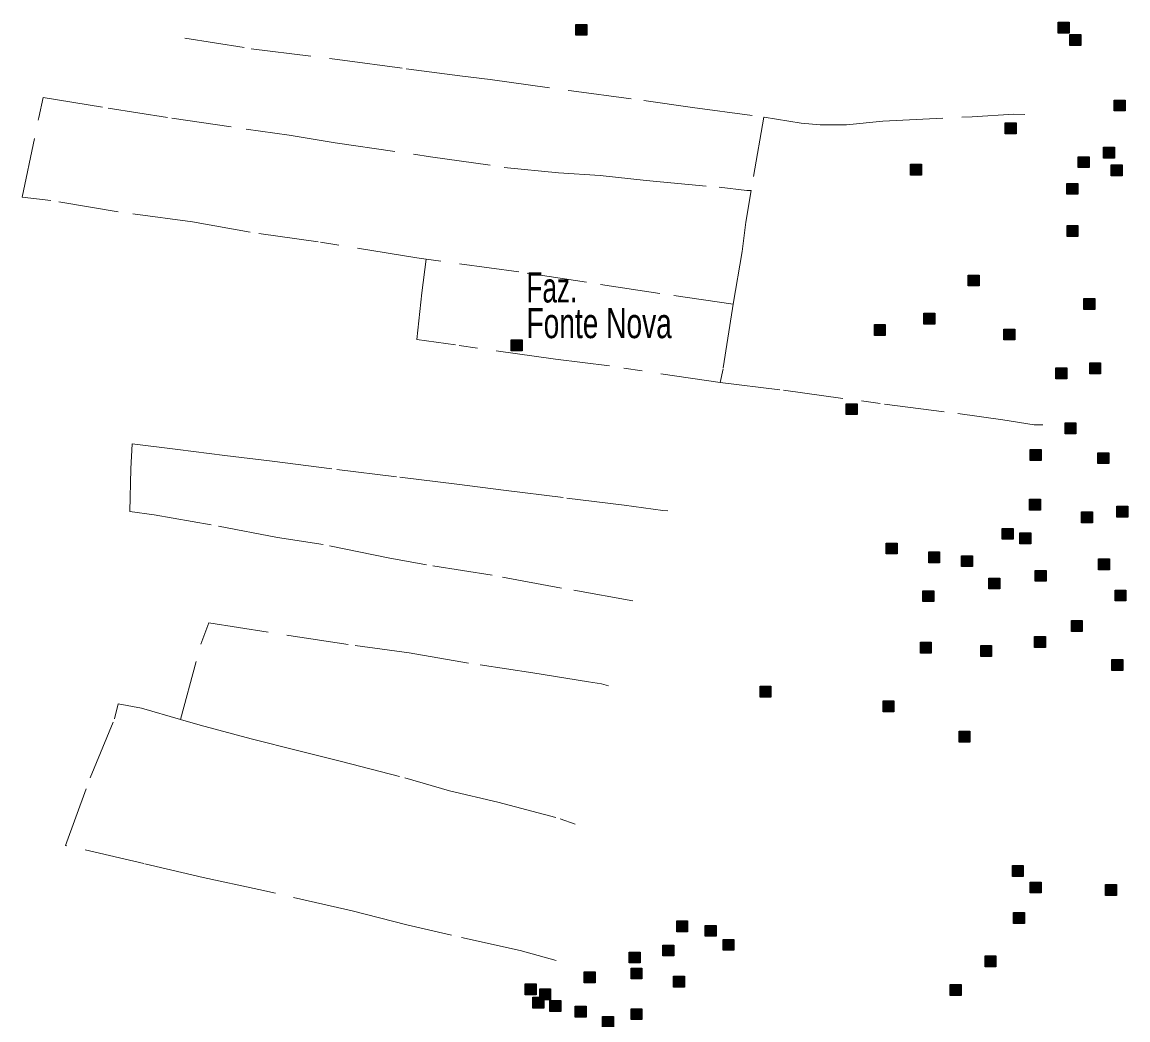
# Model space of a CAD drawing. Extents: x 445.6 to 500, y 8618.1 to 8673.4.
# Drawn here: x 494.02 to 499.91, y 8658.81 to 8664.13 of the extents above; entities that cross this region are included whole.
import ezdxf

# ---------------------------------------------------------------- set-up
doc = ezdxf.new("R2010")
doc.units = 0
doc.header["$LTSCALE"] = 0.064
doc.linetypes.add('DOT_DASHED', pattern=[7.7, 5, -1.2, 0.3, -1.2])
doc.layers.add('2', color=7, linetype='Continuous', lineweight=25)
doc.layers.add('22', color=7, linetype='DOT_DASHED', lineweight=13)
doc.layers.add('61', color=7, linetype='Continuous')

msp = doc.modelspace()

# ---------------------------------------------------------------- hatches: boundary and pattern name
at = {"layer": '2'}
for points in [[(496.9698, 8664.1133), (497.0278, 8664.1133), (497.0278, 8664.0553), (496.9698, 8664.0553)], [(499.5395, 8664.1252), (499.5975, 8664.1252), (499.5975, 8664.0672), (499.5395, 8664.0672)], [(499.602, 8664.0591), (499.66, 8664.0591), (499.66, 8664.0011), (499.602, 8664.0011)], [(499.8385, 8663.7101), (499.8965, 8663.7101), (499.8965, 8663.6521), (499.8385, 8663.6521)], [(499.2575, 8663.5882), (499.3155, 8663.5882), (499.3155, 8663.5302), (499.2575, 8663.5302)], [(499.7811, 8663.4594), (499.8391, 8663.4594), (499.8391, 8663.4014), (499.7811, 8663.4014)], [(499.646, 8663.4086), (499.704, 8663.4086), (499.704, 8663.3506), (499.646, 8663.3506)], [(498.7525, 8663.368), (498.8105, 8663.368), (498.8105, 8663.31), (498.7525, 8663.31)], [(499.8216, 8663.3646), (499.8796, 8663.3646), (499.8796, 8663.3066), (499.8216, 8663.3066)], [(499.5852, 8663.2663), (499.6432, 8663.2663), (499.6432, 8663.2083), (499.5852, 8663.2083)], [(499.5867, 8663.0413), (499.6447, 8663.0413), (499.6447, 8662.9833), (499.5867, 8662.9833)], [(499.0599, 8662.7784), (499.1179, 8662.7784), (499.1179, 8662.7204), (499.0599, 8662.7204)], [(499.6764, 8662.6531), (499.7344, 8662.6531), (499.7344, 8662.5951), (499.6764, 8662.5951)], [(498.8234, 8662.5752), (498.8814, 8662.5752), (498.8814, 8662.5172), (498.8234, 8662.5172)], [(498.56, 8662.5142), (498.618, 8662.5142), (498.618, 8662.4562), (498.56, 8662.4562)], [(499.2507, 8662.4905), (499.3087, 8662.4905), (499.3087, 8662.4325), (499.2507, 8662.4325)], [(496.626, 8662.4328), (496.684, 8662.4328), (496.684, 8662.3748), (496.626, 8662.3748)], [(499.5277, 8662.2838), (499.5857, 8662.2838), (499.5857, 8662.2258), (499.5277, 8662.2258)], [(499.7075, 8662.31), (499.7655, 8662.31), (499.7655, 8662.252), (499.7075, 8662.252)], [(498.4104, 8662.0931), (498.4684, 8662.0931), (498.4684, 8662.0351), (498.4104, 8662.0351)], [(499.5757, 8661.9915), (499.6337, 8661.9915), (499.6337, 8661.9335), (499.5757, 8661.9335)], [(499.39, 8661.8492), (499.448, 8661.8492), (499.448, 8661.7912), (499.39, 8661.7912)], [(499.7514, 8661.8322), (499.8094, 8661.8322), (499.8094, 8661.7742), (499.7514, 8661.7742)], [(499.3866, 8661.5849), (499.4446, 8661.5849), (499.4446, 8661.5269), (499.3866, 8661.5269)], [(499.6636, 8661.5172), (499.7216, 8661.5172), (499.7216, 8661.4592), (499.6636, 8661.4592)], [(499.8527, 8661.5477), (499.9107, 8661.5477), (499.9107, 8661.4897), (499.8527, 8661.4897)], [(499.2413, 8661.4291), (499.2993, 8661.4291), (499.2993, 8661.3711), (499.2413, 8661.3711)], [(499.3359, 8661.4054), (499.3939, 8661.4054), (499.3939, 8661.3474), (499.3359, 8661.3474)], [(498.6232, 8661.3511), (498.6812, 8661.3511), (498.6812, 8661.2931), (498.6232, 8661.2931)], [(498.8495, 8661.3037), (498.9075, 8661.3037), (498.9075, 8661.2457), (498.8495, 8661.2457)], [(499.0252, 8661.2834), (499.0832, 8661.2834), (499.0832, 8661.2254), (499.0252, 8661.2254)], [(499.7548, 8661.2664), (499.8128, 8661.2664), (499.8128, 8661.2084), (499.7548, 8661.2084)], [(499.1704, 8661.1648), (499.2284, 8661.1648), (499.2284, 8661.1068), (499.1704, 8661.1068)], [(499.417, 8661.2055), (499.475, 8661.2055), (499.475, 8661.1475), (499.417, 8661.1475)], [(498.8191, 8661.097), (498.8771, 8661.097), (498.8771, 8661.039), (498.8191, 8661.039)], [(499.8426, 8661.1004), (499.9006, 8661.1004), (499.9006, 8661.0424), (499.8426, 8661.0424)], [(499.6095, 8660.9378), (499.6675, 8660.9378), (499.6675, 8660.8798), (499.6095, 8660.8798)], [(498.8056, 8660.8226), (498.8636, 8660.8226), (498.8636, 8660.7646), (498.8056, 8660.7646)], [(499.1265, 8660.8057), (499.1845, 8660.8057), (499.1845, 8660.7477), (499.1265, 8660.7477)], [(499.4136, 8660.8531), (499.4716, 8660.8531), (499.4716, 8660.7951), (499.4136, 8660.7951)], [(499.8257, 8660.7311), (499.8837, 8660.7311), (499.8837, 8660.6731), (499.8257, 8660.6731)], [(497.951, 8660.5888), (498.009, 8660.5888), (498.009, 8660.5308), (497.951, 8660.5308)], [(498.6063, 8660.5109), (498.6643, 8660.5109), (498.6643, 8660.4529), (498.6063, 8660.4529)], [(499.0116, 8660.3483), (499.0696, 8660.3483), (499.0696, 8660.2903), (499.0116, 8660.2903)], [(499.2954, 8659.6335), (499.3534, 8659.6335), (499.3534, 8659.5755), (499.2954, 8659.5755)], [(499.3899, 8659.5454), (499.4479, 8659.5454), (499.4479, 8659.4874), (499.3899, 8659.4874)], [(499.7919, 8659.5319), (499.8499, 8659.5319), (499.8499, 8659.4739), (499.7919, 8659.4739)], [(497.5073, 8659.3386), (497.5653, 8659.3386), (497.5653, 8659.2806), (497.5073, 8659.2806)], [(499.3021, 8659.3828), (499.3601, 8659.3828), (499.3601, 8659.3248), (499.3021, 8659.3248)], [(497.6593, 8659.3149), (497.7173, 8659.3149), (497.7173, 8659.2569), (497.6593, 8659.2569)], [(497.7539, 8659.2404), (497.8119, 8659.2404), (497.8119, 8659.1824), (497.7539, 8659.1824)], [(497.254, 8659.1726), (497.312, 8659.1726), (497.312, 8659.1146), (497.254, 8659.1146)], [(497.433, 8659.2099), (497.491, 8659.2099), (497.491, 8659.1519), (497.433, 8659.1519)], [(499.1501, 8659.1524), (499.2081, 8659.1524), (499.2081, 8659.0944), (499.1501, 8659.0944)], [(497.0141, 8659.0676), (497.0721, 8659.0676), (497.0721, 8659.0096), (497.0141, 8659.0096)], [(497.2641, 8659.0879), (497.3221, 8659.0879), (497.3221, 8659.0299), (497.2641, 8659.0299)], [(497.4904, 8659.0439), (497.5484, 8659.0439), (497.5484, 8658.9859), (497.4904, 8658.9859)], [(496.7, 8659.0032), (496.758, 8659.0032), (496.758, 8658.9452), (496.7, 8658.9452)], [(496.7777, 8658.9761), (496.8357, 8658.9761), (496.8357, 8658.9181), (496.7777, 8658.9181)], [(498.9643, 8659), (499.0223, 8659), (499.0223, 8658.942), (498.9643, 8658.942)], [(496.7405, 8658.9321), (496.7985, 8658.9321), (496.7985, 8658.8741), (496.7405, 8658.8741)], [(496.8317, 8658.9151), (496.8897, 8658.9151), (496.8897, 8658.8571), (496.8317, 8658.8571)], [(496.9669, 8658.8847), (497.0249, 8658.8847), (497.0249, 8658.8267), (496.9669, 8658.8267)], [(497.2641, 8658.8711), (497.3221, 8658.8711), (497.3221, 8658.8131), (497.2641, 8658.8131)], [(497.1121, 8658.8304), (497.1701, 8658.8304), (497.1701, 8658.7724), (497.1121, 8658.7724)]]:
    msp.add_hatch(color=256, dxfattribs=at).paths.add_polyline_path(points)

# ---------------------------------------------------------------- linework, layer by layer
for points in [[(496.9698, 8664.1133), (497.0278, 8664.1133), (497.0278, 8664.0553), (496.9698, 8664.0553)], [(499.5395, 8664.1252), (499.5975, 8664.1252), (499.5975, 8664.0672), (499.5395, 8664.0672)], [(499.602, 8664.0591), (499.66, 8664.0591), (499.66, 8664.0011), (499.602, 8664.0011)], [(499.8385, 8663.7101), (499.8965, 8663.7101), (499.8965, 8663.6521), (499.8385, 8663.6521)], [(499.2575, 8663.5882), (499.3155, 8663.5882), (499.3155, 8663.5302), (499.2575, 8663.5302)], [(499.7811, 8663.4594), (499.8391, 8663.4594), (499.8391, 8663.4014), (499.7811, 8663.4014)], [(499.646, 8663.4086), (499.704, 8663.4086), (499.704, 8663.3506), (499.646, 8663.3506)], [(498.7525, 8663.368), (498.8105, 8663.368), (498.8105, 8663.31), (498.7525, 8663.31)], [(499.8216, 8663.3646), (499.8796, 8663.3646), (499.8796, 8663.3066), (499.8216, 8663.3066)], [(499.5852, 8663.2663), (499.6432, 8663.2663), (499.6432, 8663.2083), (499.5852, 8663.2083)], [(499.5867, 8663.0413), (499.6447, 8663.0413), (499.6447, 8662.9833), (499.5867, 8662.9833)], [(499.0599, 8662.7784), (499.1179, 8662.7784), (499.1179, 8662.7204), (499.0599, 8662.7204)], [(499.6764, 8662.6531), (499.7344, 8662.6531), (499.7344, 8662.5951), (499.6764, 8662.5951)], [(498.8234, 8662.5752), (498.8814, 8662.5752), (498.8814, 8662.5172), (498.8234, 8662.5172)], [(498.56, 8662.5142), (498.618, 8662.5142), (498.618, 8662.4562), (498.56, 8662.4562)], [(499.2507, 8662.4905), (499.3087, 8662.4905), (499.3087, 8662.4325), (499.2507, 8662.4325)], [(496.626, 8662.4328), (496.684, 8662.4328), (496.684, 8662.3748), (496.626, 8662.3748)], [(499.5277, 8662.2838), (499.5857, 8662.2838), (499.5857, 8662.2258), (499.5277, 8662.2258)], [(499.7075, 8662.31), (499.7655, 8662.31), (499.7655, 8662.252), (499.7075, 8662.252)], [(498.4104, 8662.0931), (498.4684, 8662.0931), (498.4684, 8662.0351), (498.4104, 8662.0351)], [(499.5757, 8661.9915), (499.6337, 8661.9915), (499.6337, 8661.9335), (499.5757, 8661.9335)], [(499.39, 8661.8492), (499.448, 8661.8492), (499.448, 8661.7912), (499.39, 8661.7912)], [(499.7514, 8661.8322), (499.8094, 8661.8322), (499.8094, 8661.7742), (499.7514, 8661.7742)], [(499.3866, 8661.5849), (499.4446, 8661.5849), (499.4446, 8661.5269), (499.3866, 8661.5269)], [(499.6636, 8661.5172), (499.7216, 8661.5172), (499.7216, 8661.4592), (499.6636, 8661.4592)], [(499.8527, 8661.5477), (499.9107, 8661.5477), (499.9107, 8661.4897), (499.8527, 8661.4897)], [(499.2413, 8661.4291), (499.2993, 8661.4291), (499.2993, 8661.3711), (499.2413, 8661.3711)], [(499.3359, 8661.4054), (499.3939, 8661.4054), (499.3939, 8661.3474), (499.3359, 8661.3474)], [(498.6232, 8661.3511), (498.6812, 8661.3511), (498.6812, 8661.2931), (498.6232, 8661.2931)], [(498.8495, 8661.3037), (498.9075, 8661.3037), (498.9075, 8661.2457), (498.8495, 8661.2457)], [(499.0252, 8661.2834), (499.0832, 8661.2834), (499.0832, 8661.2254), (499.0252, 8661.2254)], [(499.7548, 8661.2664), (499.8128, 8661.2664), (499.8128, 8661.2084), (499.7548, 8661.2084)], [(499.1704, 8661.1648), (499.2284, 8661.1648), (499.2284, 8661.1068), (499.1704, 8661.1068)], [(499.417, 8661.2055), (499.475, 8661.2055), (499.475, 8661.1475), (499.417, 8661.1475)], [(498.8191, 8661.097), (498.8771, 8661.097), (498.8771, 8661.039), (498.8191, 8661.039)], [(499.8426, 8661.1004), (499.9006, 8661.1004), (499.9006, 8661.0424), (499.8426, 8661.0424)], [(499.6095, 8660.9378), (499.6675, 8660.9378), (499.6675, 8660.8798), (499.6095, 8660.8798)], [(498.8056, 8660.8226), (498.8636, 8660.8226), (498.8636, 8660.7646), (498.8056, 8660.7646)], [(499.1265, 8660.8057), (499.1845, 8660.8057), (499.1845, 8660.7477), (499.1265, 8660.7477)], [(499.4136, 8660.8531), (499.4716, 8660.8531), (499.4716, 8660.7951), (499.4136, 8660.7951)], [(499.8257, 8660.7311), (499.8837, 8660.7311), (499.8837, 8660.6731), (499.8257, 8660.6731)], [(497.951, 8660.5888), (498.009, 8660.5888), (498.009, 8660.5308), (497.951, 8660.5308)], [(498.6063, 8660.5109), (498.6643, 8660.5109), (498.6643, 8660.4529), (498.6063, 8660.4529)], [(499.0116, 8660.3483), (499.0696, 8660.3483), (499.0696, 8660.2903), (499.0116, 8660.2903)], [(499.2954, 8659.6335), (499.3534, 8659.6335), (499.3534, 8659.5755), (499.2954, 8659.5755)], [(499.3899, 8659.5454), (499.4479, 8659.5454), (499.4479, 8659.4874), (499.3899, 8659.4874)], [(499.7919, 8659.5319), (499.8499, 8659.5319), (499.8499, 8659.4739), (499.7919, 8659.4739)], [(497.5073, 8659.3386), (497.5653, 8659.3386), (497.5653, 8659.2806), (497.5073, 8659.2806)], [(499.3021, 8659.3828), (499.3601, 8659.3828), (499.3601, 8659.3248), (499.3021, 8659.3248)], [(497.6593, 8659.3149), (497.7173, 8659.3149), (497.7173, 8659.2569), (497.6593, 8659.2569)], [(497.7539, 8659.2404), (497.8119, 8659.2404), (497.8119, 8659.1824), (497.7539, 8659.1824)], [(497.254, 8659.1726), (497.312, 8659.1726), (497.312, 8659.1146), (497.254, 8659.1146)], [(497.433, 8659.2099), (497.491, 8659.2099), (497.491, 8659.1519), (497.433, 8659.1519)], [(499.1501, 8659.1524), (499.2081, 8659.1524), (499.2081, 8659.0944), (499.1501, 8659.0944)], [(497.0141, 8659.0676), (497.0721, 8659.0676), (497.0721, 8659.0096), (497.0141, 8659.0096)], [(497.2641, 8659.0879), (497.3221, 8659.0879), (497.3221, 8659.0299), (497.2641, 8659.0299)], [(497.4904, 8659.0439), (497.5484, 8659.0439), (497.5484, 8658.9859), (497.4904, 8658.9859)], [(496.7, 8659.0032), (496.758, 8659.0032), (496.758, 8658.9452), (496.7, 8658.9452)], [(496.7777, 8658.9761), (496.8357, 8658.9761), (496.8357, 8658.9181), (496.7777, 8658.9181)], [(498.9643, 8659), (499.0223, 8659), (499.0223, 8658.942), (498.9643, 8658.942)], [(496.7405, 8658.9321), (496.7985, 8658.9321), (496.7985, 8658.8741), (496.7405, 8658.8741)], [(496.8317, 8658.9151), (496.8897, 8658.9151), (496.8897, 8658.8571), (496.8317, 8658.8571)], [(496.9669, 8658.8847), (497.0249, 8658.8847), (497.0249, 8658.8267), (496.9669, 8658.8267)], [(497.2641, 8658.8711), (497.3221, 8658.8711), (497.3221, 8658.8131), (497.2641, 8658.8131)], [(497.1121, 8658.8304), (497.1701, 8658.8304), (497.1701, 8658.7724), (497.1121, 8658.7724)]]:
    msp.add_lwpolyline(points, close=True, dxfattribs=at)
at = {"layer": '22'}
msp.add_line((497.9708, 8663.6193), (497.9042, 8663.2278), dxfattribs=at)
for points in [[(494.8873, 8664.0395), (495.2402, 8663.9834), (495.7267, 8663.922), (496.0663, 8663.8766), (496.3523, 8663.8392), (496.5127, 8663.8205), (496.9473, 8663.7586), (497.3322, 8663.7079), (497.5916, 8663.6705), (497.9708, 8663.6193)], [(496.1722, 8662.8627), (496.122, 8662.8695), (495.598, 8662.9557), (495.2348, 8663.0058), (494.9277, 8663.0619), (494.5319, 8663.115), (494.1735, 8663.1747), (494.02, 8663.1924), (494.1086, 8663.6171), (494.1322, 8663.7233), (494.4777, 8663.6673), (494.8173, 8663.6142), (495.213, 8663.5552), (495.4434, 8663.5227), (495.6885, 8663.4815), (496.1958, 8663.4078), (496.5886, 8663.3517), (496.878, 8663.3222), (497.0995, 8663.3075), (497.3446, 8663.281), (497.7331, 8663.2455), (497.8808, 8663.2278), (497.9042, 8663.2278)], [(497.9708, 8663.6193), (497.9725, 8663.6191), (498.1704, 8663.5871), (498.272, 8663.5791), (498.411, 8663.5791), (498.6061, 8663.5978), (499.0813, 8663.6217), (499.3032, 8663.6351), (499.3618, 8663.6338)], [(497.9042, 8663.2278), (497.8757, 8663.0601), (497.855, 8662.9038), (497.8081, 8662.6229)], [(497.7394, 8662.2055), (497.1488, 8662.294), (496.8623, 8662.3294), (496.3291, 8662.4059), (496.1224, 8662.4354), (496.149, 8662.6831), (496.1722, 8662.8627)], [(497.8081, 8662.6229), (497.417, 8662.6807), (497.0272, 8662.7397), (496.6669, 8662.7957), (496.1722, 8662.8627)], [(497.8081, 8662.6229), (497.8044, 8662.6007), (497.7542, 8662.2792), (497.7394, 8662.2055)], [(497.7394, 8662.2055), (498.0755, 8662.1646), (498.614, 8662.0907), (499.0046, 8662.0404), (499.2443, 8662.0079), (499.4115, 8661.9811), (499.4569, 8661.9811)], [(497.2741, 8661.0441), (496.8938, 8661.1113), (496.5243, 8661.1799), (496.1738, 8661.2343), (495.9701, 8661.2722), (495.6229, 8661.3436), (495.3813, 8661.3814), (495.0273, 8661.4476), (494.7242, 8661.502), (494.5939, 8661.5186), (494.5987, 8661.7457), (494.6058, 8661.8795), (494.8497, 8661.8488), (495.1008, 8661.818), (495.3518, 8661.7872), (495.6964, 8661.742), (496.0328, 8661.7018), (496.3359, 8661.664), (496.5846, 8661.6332), (496.9222, 8661.5905), (497.2277, 8661.5526), (497.4337, 8661.5243), (497.4591, 8661.522)], [(494.8632, 8660.4116), (494.9716, 8660.8124), (495.0155, 8660.9257), (495.4412, 8660.8587), (495.7946, 8660.8046), (496.0827, 8660.7661), (496.4594, 8660.7016), (496.7406, 8660.6604), (497.0372, 8660.6115), (497.1069, 8660.6012), (497.1435, 8660.5899)], [(496.8654, 8659.1276), (496.6737, 8659.1805), (496.3073, 8659.2629), (496.07, 8659.317), (495.7785, 8659.3918), (495.2818, 8659.5057), (494.9851, 8659.5701), (494.6678, 8659.6448), (494.2512, 8659.7408), (494.3828, 8660.1015), (494.5119, 8660.4147), (494.5325, 8660.4945), (494.6563, 8660.4713), (494.8632, 8660.4116)], [(494.8632, 8660.4116), (494.9685, 8660.3812), (495.2394, 8660.309), (495.4948, 8660.2446), (495.7207, 8660.1877), (496.0586, 8660.1001), (496.296, 8660.0306), (496.5539, 8659.9713), (496.8856, 8659.8829), (496.9659, 8659.8545)]]:
    msp.add_lwpolyline(points, dxfattribs=at)

# ---------------------------------------------------------------- texts
at = {"layer": '61'}
for s, width, p in [('Faz.', 0.65, (496.7069, 8662.6322)), ('Fonte Nova', 0.7, (496.7069, 8662.4422))]:
    msp.add_text(s, height=0.16, dxfattribs=dict(at, width=width)).set_placement(p)

doc.saveas('drawing.dxf')
